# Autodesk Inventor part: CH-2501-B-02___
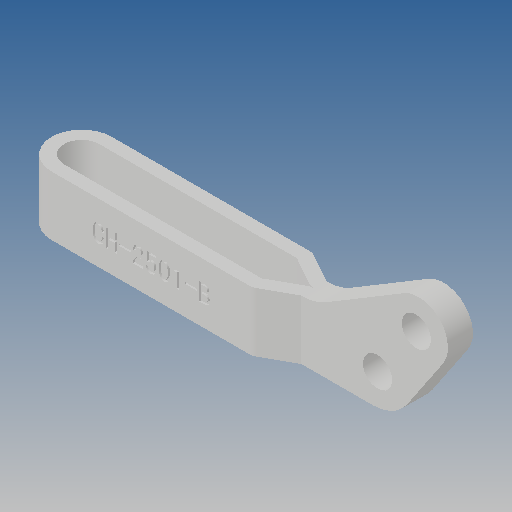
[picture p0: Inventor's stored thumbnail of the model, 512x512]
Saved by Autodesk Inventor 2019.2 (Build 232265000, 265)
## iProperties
Created: 2012-09
Part Number: CH-2501-B-02___
Material: Ogólny
Document SubType Name: Modeling
Designer: CADENGINEERING4
Density: 1 g/cm^3
Appearance: Domyślna
Author: CADENGINEERING4
Revision Number: ÈÎºÎ
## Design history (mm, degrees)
feature "NONE"
node "Bryła1"
